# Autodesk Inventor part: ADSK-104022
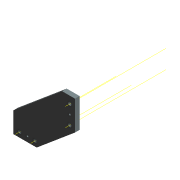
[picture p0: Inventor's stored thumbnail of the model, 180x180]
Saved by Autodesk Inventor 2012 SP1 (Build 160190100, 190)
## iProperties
Shininess: 0.0
Created: 2001-01
Part Number: ADSK-104022
Document SubType Name: Modeling
Stock Number: ADSK-104022
Density: 1 g/cm^3
Material: Default
Density: 0.0
Volumn: 0.0
Area: 0.0
PropertySet Name: Model Information
Control State: 0
Master: False
Checked Out: False
Author: gao
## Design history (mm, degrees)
node "Extrusion1" dims "d4" = 19.05, "d5" = 0
  sketch "Sketch1"
    geometry: L1 (186.32, -21.65)-(-93.08, -21.65) reference; L2 (-93.08, -21.65)-(-93.08, 42.485); L3 (-93.08, 42.485)-(133.192, 232.35); L4 (133.192, 232.35)-(186.32, 232.35); L5 (186.32, -21.65)-(186.32, 232.35)
    constraints: 10 end point, 2 horizontal, 1 parallel, 1 perpendicular
    dimensions: "d0" = 279.4 distance of L1.start L1.end; "d1" = 254 distance of L1.start L4.end; "d2" = 40 deg angle of L4 L3; "d3" = 64.135 distance of L1.end L2.end
sketch "Sketch2"
  geometry: L1 (186.32, -21.65)-(-93.08, -21.65) reference; L2 (186.32, 232.35)-(186.32, -21.65) reference; L3 (133.192, 232.35)-(186.32, 232.35) reference; L4 (-93.08, 42.485)-(133.192, 232.35) reference; L5 (-93.08, -21.65)-(-93.08, 42.485) reference
node "Extrusion2" dims "d7" = 19.05, "d8" = 0
  sketch "Sketch3"
    geometry: L1 (186.32, -21.65)-(-93.08, -21.65) reference; L2 (186.32, 232.35)-(186.32, -21.65) reference; L3 (-93.08, 42.485)-(133.192, 232.35) reference; L4 (186.32, 111.142)-(28.064, -21.65)
    constraints: 2 end point, 2 point on line
    dimensions: "d6" = 127 distance between parallel lines of L4 L3
node "Hole1" dims "d9" = 13.462, "d10" = 9.525, "d11" = 6.35, "d12" = 60 deg, "d13" = 19.05, "d14" = 118 deg
  sketch "Sketch4"
    geometry: C1 r 5.296 at (165.1, 127) reference; C2 r 5.296 at (165.1, 203.2) reference; C3 r 5.296 at (22.225, 0) reference; C4 r 5.296 at (-41.275, 0) reference; 4 further points
    constraints: 4 coincident
node "Extrusion3" dims "d16" = 19.05, "d17" = 0
  sketch "Sketch5"
    geometry: L1 (-93.08, 42.485)-(133.192, 232.35) reference; L2 (-93.08, -21.65)-(-93.08, 42.485) reference; L3 (28.064, -21.65)-(-93.08, -21.65) reference; L4 (-67.68, -21.65)-(-67.68, 63.798)
    constraints: 2 end point, 2 point on line, 1 perpendicular
    dimensions: "d15" = 25.4 distance between parallel lines of L4 L2
workaxis "Work Axis1"
workaxis "Work Axis2"
workaxis "Work Axis3"
workaxis "Work Axis4"
node "Hole2" dims "d20" = 7.112, "d21" = 9.525, "d22" = 6.35, "d23" = 60 deg, "d24" = 19.05, "d25" = 118 deg
  sketch "Sketch6"
    geometry: C1 r 6.731 at (-41.275, 0) reference; C2 r 6.731 at (165.1, 127) reference; 2 further points
    dimensions: "d18" = 31.75 distance of point (-9.525, 0) C1.centre; "d19" = 38.1 distance of point (165.1, 165.1) C2.centre
body "Solid1"
